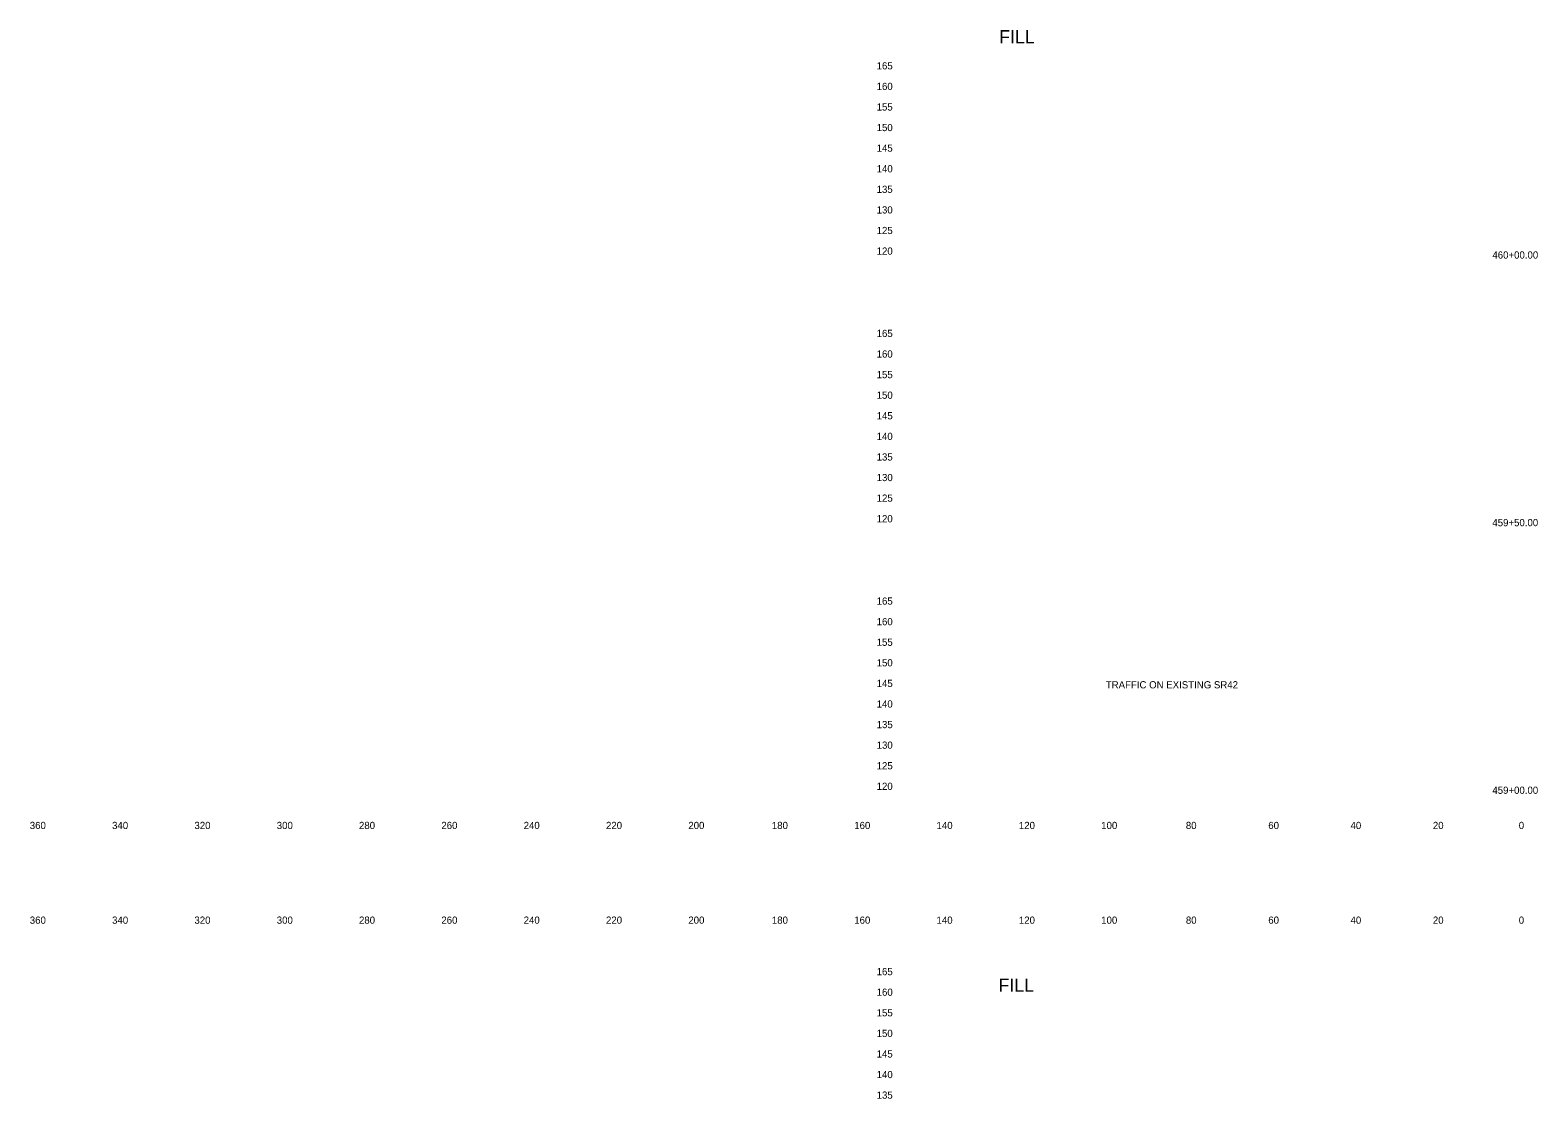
# Model space of a CAD drawing. Extents: x 21281 to 22024, y 6472 to 15198.
# Drawn here: x 21280.5 to 21646.7, y 7559.8 to 7819.4 of the extents above; entities that cross this region are included whole.
import ezdxf

# ---------------------------------------------------------------- set-up
doc = ezdxf.new("R2010")
doc.units = 0
for name, color, linetype in [('XS_SHEET_LABELS_ELEVATION', 7, 'Continuous'), ('XS_SHEET_LABELS_OFFSET', 7, 'Continuous'), ('XS_SHEET_LABELS_STATION', 7, 'Continuous')]:
    doc.layers.add(name, color=color, linetype=linetype)

msp = doc.modelspace()

# ---------------------------------------------------------------- texts
at = {"layer": 'XS_SHEET_LABELS_ELEVATION'}
for s, p in [('  165  ', (21484.84, 7809.84)), ('  160  ', (21484.84, 7804.84)), ('  155  ', (21484.84, 7799.84)), ('  150  ', (21484.84, 7794.84)), ('  145  ', (21484.84, 7789.84)), ('  140  ', (21484.84, 7784.84)), ('  135  ', (21484.84, 7779.84)), ('  130  ', (21484.84, 7774.84)), ('  125  ', (21484.84, 7769.84)), ('  120  ', (21484.84, 7764.84)), ('  165  ', (21484.84, 7744.84)), ('  160  ', (21484.84, 7739.84)), ('  155  ', (21484.84, 7734.84)), ('  150  ', (21484.84, 7729.84)), ('  145  ', (21484.84, 7724.84)), ('  140  ', (21484.84, 7719.84)), ('  135  ', (21484.84, 7714.84)), ('  130  ', (21484.84, 7709.84)), ('  125  ', (21484.84, 7704.84)), ('  120  ', (21484.84, 7699.84)), ('  165  ', (21484.84, 7679.84)), ('  160  ', (21484.84, 7674.84)), ('  155  ', (21484.84, 7669.84)), ('  150  ', (21484.84, 7664.84)), ('  145  ', (21484.84, 7659.84)), ('  140  ', (21484.84, 7654.84)), ('  135  ', (21484.84, 7649.84)), ('  130  ', (21484.84, 7644.84)), ('  125  ', (21484.84, 7639.84)), ('  120  ', (21484.84, 7634.84)), ('  165  ', (21484.84, 7589.84)), ('  160  ', (21484.84, 7584.84)), ('  155  ', (21484.84, 7579.84)), ('  150  ', (21484.84, 7574.84)), ('  145  ', (21484.84, 7569.84)), ('  140  ', (21484.84, 7564.84)), ('  135  ', (21484.84, 7559.84))]:
    msp.add_text(s, height=1.75, dxfattribs=at).set_placement(p)
at = {"layer": 'XS_SHEET_LABELS_OFFSET'}
for s, height, p in [('FILL', 3.222, (21515.91, 7816.15)), ('  360  ', 1.75, (21279.14, 7625.34)), ('  340  ', 1.75, (21299.13, 7625.34)), ('  320  ', 1.75, (21319.13, 7625.34)), ('  300  ', 1.75, (21339.13, 7625.34)), ('  280  ', 1.75, (21359.1, 7625.34)), ('  260  ', 1.75, (21379.11, 7625.34)), ('  240  ', 1.75, (21399.1, 7625.34)), ('  220  ', 1.75, (21419.1, 7625.34)), ('  200  ', 1.75, (21439.1, 7625.34)), ('  180  ', 1.75, (21459.39, 7625.34)), ('  160  ', 1.75, (21479.4, 7625.34)), ('  140  ', 1.75, (21499.39, 7625.34)), ('  120  ', 1.75, (21519.39, 7625.34)), ('  100  ', 1.75, (21539.39, 7625.34)), ('  80  ', 1.75, (21559.95, 7625.34)), ('  60  ', 1.75, (21579.97, 7625.34)), ('  40  ', 1.75, (21599.95, 7625.34)), ('  20  ', 1.75, (21619.95, 7625.34)), ('  0  ', 1.75, (21640.81, 7625.34)), ('  0  ', 1.75, (21640.81, 7625.34)), ('  360  ', 1.75, (21279.14, 7602.34)), ('  340  ', 1.75, (21299.13, 7602.34)), ('  320  ', 1.75, (21319.13, 7602.34)), ('  300  ', 1.75, (21339.13, 7602.34)), ('  280  ', 1.75, (21359.1, 7602.34)), ('  260  ', 1.75, (21379.11, 7602.34)), ('  240  ', 1.75, (21399.1, 7602.34)), ('  220  ', 1.75, (21419.1, 7602.34)), ('  200  ', 1.75, (21439.1, 7602.34)), ('  180  ', 1.75, (21459.39, 7602.34)), ('  160  ', 1.75, (21479.4, 7602.34)), ('  140  ', 1.75, (21499.39, 7602.34)), ('  120  ', 1.75, (21519.39, 7602.34)), ('  100  ', 1.75, (21539.39, 7602.34)), ('  80  ', 1.75, (21559.95, 7602.34)), ('  60  ', 1.75, (21579.97, 7602.34)), ('  40  ', 1.75, (21599.95, 7602.34)), ('  20  ', 1.75, (21619.95, 7602.34)), ('  0  ', 1.75, (21640.81, 7602.34)), ('  0  ', 1.75, (21640.81, 7602.34)), ('FILL', 3.222, (21515.74, 7585.81))]:
    msp.add_text(s, height=height, dxfattribs=at).set_placement(p)
at = {"layer": 'XS_SHEET_LABELS_STATION'}
for s, p in [('  460+00.00  ', (21634.41, 7763.89)), ('  459+50.00  ', (21634.4, 7698.89)), ('TRAFFIC ON EXISTING SR42', (21541.8, 7659.5)), ('  459+00.00  ', (21634.4, 7633.89))]:
    msp.add_text(s, height=1.75, dxfattribs=at).set_placement(p)

doc.saveas('drawing.dxf')
